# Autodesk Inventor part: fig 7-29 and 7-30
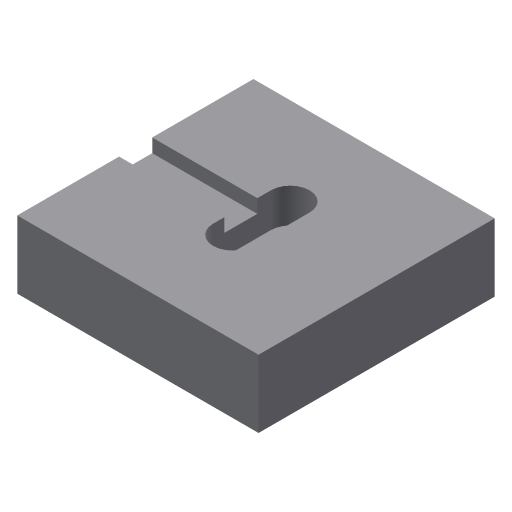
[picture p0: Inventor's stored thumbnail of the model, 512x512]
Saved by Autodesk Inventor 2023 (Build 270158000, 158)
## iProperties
Created: 2004-05
Part Number: fig 7-29 and 7-30
Document SubType Name: Modeling
Designer: CADCIM Technologies
Manufacturer: Standard
Standards Organization: Custom
Density: 1 g/cm^3
Material: Generic
Appearance: Default
Author: CADCIM Technologies
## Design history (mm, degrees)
sketch "Sketch1"
  geometry: L1 (-30.233, -25.517)-(22.302, -25.517); L2 (22.302, -25.517)-(22.302, 25.904); L3 (22.302, 25.904)-(-30.233, 25.904); L4 (-30.233, 25.904)-(-30.233, -25.517)
  constraints: 8 end point, 2 parallel, 1 horizontal, 1 perpendicular
extrude "Extrusion1" new body sketch "Sketch1" distance "d0" = 14.75; taper "d1" = 0 deg
sketch "Sketch2"
  geometry: L1 (1.047, -5.75)-(1.047, 6.846); L2 (-7.35, 6.845)-(-7.35, -5.75); A1 r 4.198 centre (-3.152, 6.846) between (1.047, 6.846) and (-7.35, 6.845); A2 r 4.198 centre (-3.152, -5.75) between (-7.35, -5.75) and (1.047, -5.75)
  constraints: 4 end point, 4 point on circle, 4 tangent, 2 centre point, 1 parallel
extrude "Extrusion2" cut sketch "Sketch2" distance "d2" = 7.5; taper "d3" = 0 deg
sketch "Sketch3"
  geometry: L1 (-7.5, 0)-(-7.5, 12.595) reference; L2 (-7.5, 0)-(0, 0) reference; L3 (-7.5, 2.416)-(-4.537, 2.416); L4 (-4.537, 2.416)-(-4.537, 9.616); L5 (-4.537, 9.616)-(-7.5, 9.616)
  constraints: 6 end point, 2 perpendicular, 2 point on line, 1 parallel
extrude "Extrusion3" cut sketch "Sketch3" extent not by distance; stored distance "d4" = 6.75; taper "d5" = 0 deg
body "Solid1"
